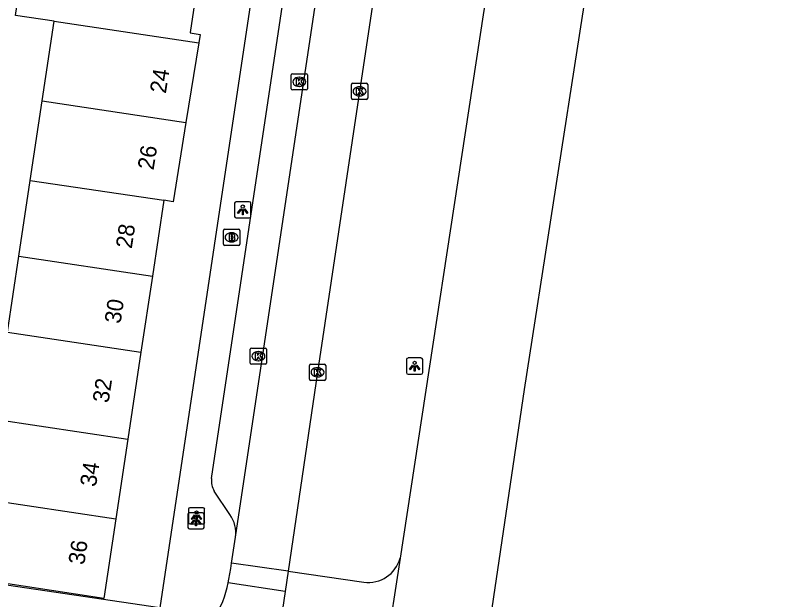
# Model space of a CAD drawing. Extents: x 164150 to 165261, y 382513 to 383432.
# Drawn here: x 164355.91 to 164402.98, y 382748.48 to 382784.41 of the extents above; entities that cross this region are included whole.
import ezdxf

# ---------------------------------------------------------------- set-up
doc = ezdxf.new("R2010")
doc.units = 0
for name, color, linetype in [('IMGEO_Brandkraan', 7, 'Continuous'), ('IMGEO_Kolk', 7, 'Continuous'), ('IMGEO_Lichtpunt', 7, 'Continuous'), ('IMGEO_Pand', 7, 'Continuous'), ('IMGEO_Pand_nummerreeks', 7, 'Continuous'), ('IMGEO_Rijbaan_lokaal_open', 7, 'Continuous'), ('IMGEO_Voetpad_open', 7, 'Continuous')]:
    doc.layers.add(name, color=color, linetype=linetype)

msp = doc.modelspace()

# ---------------------------------------------------------------- linework, layer by layer
at = {"layer": 'IMGEO_Brandkraan'}
for p, q in [((164368.711, 382770.33), (164368.711, 382771.182)), ((164368.786, 382771.256), (164369.638, 382771.256)), ((164369.712, 382771.182), (164369.712, 382770.33)), ((164369.199, 382771.036), (164369.224, 382771.036)), ((164369.638, 382770.256), (164368.786, 382770.256)), ((164369.222, 382770.476), (164369.197, 382770.476))]:
    msp.add_line(p, q, dxfattribs=at)
for points in [[(164368.711, 382770.33), (164368.711, 382771.182)], [(164368.786, 382771.256), (164369.638, 382771.256)], [(164369.712, 382771.182), (164369.712, 382770.33)], [(164369.059, 382770.956), (164369.059, 382770.556), (164369.272, 382770.556)], [(164369.29, 382770.956), (164369.059, 382770.956)], [(164369.238, 382770.875), (164369.184, 382770.875), (164369.184, 382770.799)], [(164369.184, 382770.799), (164369.237, 382770.799)], [(164369.246, 382770.723), (164369.184, 382770.723), (164369.184, 382770.642)], [(164369.184, 382770.642), (164369.246, 382770.642)], [(164369.638, 382770.256), (164368.786, 382770.256)]]:
    msp.add_lwpolyline(points, dxfattribs=at)
for centre, radius, start, end in [((164368.788, 382771.18), 0.0765, 91.552, 178.448), ((164368.788, 382771.18), 0.0765, 91.552, 178.448), ((164369.636, 382771.18), 0.0765, 1.552, 88.448), ((164369.636, 382771.18), 0.0765, 1.552, 88.448), ((164369.239, 382770.837), 0.0379, 267.8285, 90.9355), ((164369.247, 382770.682), 0.0404, 269.8759, 90.5077), ((164369.294, 382770.811), 0.145, 59.4692, 91.5367), ((164369.319, 382770.858), 0.0922, 285.5137, 58.1501), ((164369.324, 382770.666), 0.105, 301.3115, 78.989), ((164368.788, 382770.332), 0.0765, 181.552, 268.448), ((164368.788, 382770.332), 0.0765, 181.552, 268.448), ((164369.278, 382770.807), 0.251, 268.6676, 293.5347), ((164369.636, 382770.332), 0.0765, 271.552, 358.448), ((164369.636, 382770.332), 0.0765, 271.552, 358.448)]:
    msp.add_arc(centre, radius, start, end, dxfattribs=at)
for centre, major_axis, ratio, start_param, end_param in [((164369.198, 382770.756), (-0.387, 0.002), 0.722429, 4.712389, 7.853982), ((164369.223, 382770.756), (-0.39, 0.002), 0.717154, 1.570796, 4.712389)]:
    msp.add_ellipse(centre, major_axis=major_axis, ratio=ratio, start_param=start_param, end_param=end_param, dxfattribs=at)
at = {"layer": 'IMGEO_Kolk'}
for p, q in [((164372.876, 382779.894), (164372.876, 382780.746)), ((164372.951, 382780.82), (164373.803, 382780.82)), ((164373.364, 382780.6), (164373.389, 382780.6)), ((164373.877, 382780.746), (164373.877, 382779.894)), ((164373.387, 382780.04), (164373.362, 382780.04)), ((164376.58, 382779.308), (164376.58, 382780.16)), ((164376.655, 382780.234), (164377.507, 382780.234)), ((164377.068, 382780.014), (164377.093, 382780.014)), ((164377.581, 382780.16), (164377.581, 382779.308)), ((164373.803, 382779.82), (164372.951, 382779.82)), ((164377.507, 382779.234), (164376.655, 382779.234)), ((164377.091, 382779.454), (164377.066, 382779.454)), ((164370.36, 382763.027), (164370.36, 382763.879)), ((164370.435, 382763.953), (164371.287, 382763.953)), ((164370.848, 382763.733), (164370.873, 382763.733)), ((164371.361, 382763.879), (164371.361, 382763.027)), ((164370.871, 382763.173), (164370.846, 382763.173)), ((164371.287, 382762.953), (164370.435, 382762.953)), ((164373.996, 382762.035), (164373.996, 382762.887)), ((164374.071, 382762.961), (164374.923, 382762.961)), ((164374.484, 382762.741), (164374.509, 382762.741)), ((164374.997, 382762.887), (164374.997, 382762.035)), ((164374.507, 382762.181), (164374.482, 382762.181)), ((164374.923, 382761.961), (164374.071, 382761.961))]:
    msp.add_line(p, q, dxfattribs=at)
for points in [[(164372.876, 382779.894), (164372.876, 382780.746)], [(164372.951, 382780.82), (164373.803, 382780.82)], [(164373.197, 382780.52), (164373.32, 382780.52), (164373.32, 382780.369), (164373.45, 382780.52), (164373.614, 382780.52), (164373.468, 382780.369), (164373.621, 382780.12), (164373.469, 382780.12), (164373.384, 382780.284), (164373.32, 382780.217), (164373.32, 382780.12), (164373.197, 382780.12), (164373.197, 382780.52)], [(164373.877, 382780.746), (164373.877, 382779.894)], [(164376.58, 382779.308), (164376.58, 382780.16)], [(164376.655, 382780.234), (164377.507, 382780.234)], [(164377.581, 382780.16), (164377.581, 382779.308)], [(164373.803, 382779.82), (164372.951, 382779.82)], [(164376.901, 382779.934), (164377.024, 382779.934), (164377.024, 382779.783), (164377.154, 382779.934), (164377.318, 382779.934), (164377.172, 382779.783), (164377.325, 382779.534), (164377.173, 382779.534), (164377.088, 382779.698), (164377.024, 382779.631), (164377.024, 382779.534), (164376.901, 382779.534), (164376.901, 382779.934)], [(164377.507, 382779.234), (164376.655, 382779.234)], [(164370.36, 382763.027), (164370.36, 382763.879)], [(164370.435, 382763.953), (164371.287, 382763.953)], [(164370.681, 382763.653), (164370.804, 382763.653), (164370.804, 382763.502), (164370.934, 382763.653), (164371.098, 382763.653), (164370.952, 382763.502), (164371.105, 382763.253), (164370.953, 382763.253), (164370.868, 382763.417), (164370.804, 382763.35), (164370.804, 382763.253), (164370.681, 382763.253), (164370.681, 382763.653)], [(164371.361, 382763.879), (164371.361, 382763.027)], [(164371.287, 382762.953), (164370.435, 382762.953)], [(164373.996, 382762.035), (164373.996, 382762.887)], [(164374.071, 382762.961), (164374.923, 382762.961)], [(164374.317, 382762.661), (164374.44, 382762.661), (164374.44, 382762.51), (164374.57, 382762.661), (164374.734, 382762.661), (164374.588, 382762.51), (164374.741, 382762.261), (164374.589, 382762.261), (164374.504, 382762.425), (164374.44, 382762.358), (164374.44, 382762.261), (164374.317, 382762.261), (164374.317, 382762.661)], [(164374.997, 382762.887), (164374.997, 382762.035)], [(164374.923, 382761.961), (164374.071, 382761.961)]]:
    msp.add_lwpolyline(points, dxfattribs=at)
for centre, start, end in [((164372.953, 382780.744), 91.552, 178.448), ((164372.953, 382780.744), 91.552, 178.448), ((164373.801, 382780.744), 1.552, 88.448), ((164373.801, 382780.744), 1.552, 88.448), ((164376.657, 382780.158), 91.552, 178.448), ((164376.657, 382780.158), 91.552, 178.448), ((164377.505, 382780.158), 1.552, 88.448), ((164377.505, 382780.158), 1.552, 88.448), ((164372.953, 382779.896), 181.552, 268.448), ((164372.953, 382779.896), 181.552, 268.448), ((164373.801, 382779.896), 271.552, 358.448), ((164373.801, 382779.896), 271.552, 358.448), ((164376.657, 382779.31), 181.552, 268.448), ((164376.657, 382779.31), 181.552, 268.448), ((164377.505, 382779.31), 271.552, 358.448), ((164377.505, 382779.31), 271.552, 358.448), ((164370.437, 382763.877), 91.552, 178.448), ((164370.437, 382763.877), 91.552, 178.448), ((164371.285, 382763.877), 1.552, 88.448), ((164371.285, 382763.877), 1.552, 88.448), ((164370.437, 382763.029), 181.552, 268.448), ((164370.437, 382763.029), 181.552, 268.448), ((164371.285, 382763.029), 271.552, 358.448), ((164371.285, 382763.029), 271.552, 358.448), ((164374.073, 382762.885), 91.552, 178.448), ((164374.073, 382762.885), 91.552, 178.448), ((164374.921, 382762.885), 1.552, 88.448), ((164374.921, 382762.885), 1.552, 88.448), ((164374.073, 382762.037), 181.552, 268.448), ((164374.073, 382762.037), 181.552, 268.448), ((164374.921, 382762.037), 271.552, 358.448), ((164374.921, 382762.037), 271.552, 358.448)]:
    msp.add_arc(centre, 0.0765, start, end, dxfattribs=at)
for centre, major_axis, ratio, start_param, end_param in [((164373.363, 382780.32), (-0.387, 0.002), 0.722429, 4.712389, 7.853982), ((164373.388, 382780.32), (-0.39, 0.002), 0.717154, 1.570796, 4.712389), ((164377.067, 382779.734), (-0.387, 0.002), 0.722429, 4.712389, 7.853982), ((164377.092, 382779.734), (-0.39, 0.002), 0.717154, 1.570796, 4.712389), ((164370.847, 382763.453), (-0.387, 0.002), 0.722429, 4.712389, 7.853982), ((164370.872, 382763.453), (-0.39, 0.002), 0.717154, 1.570796, 4.712389), ((164374.483, 382762.461), (-0.387, 0.002), 0.722429, 4.712389, 7.853982), ((164374.508, 382762.461), (-0.39, 0.002), 0.717154, 1.570796, 4.712389)]:
    msp.add_ellipse(centre, major_axis=major_axis, ratio=ratio, start_param=start_param, end_param=end_param, dxfattribs=at)
at = {"layer": 'IMGEO_Lichtpunt'}
for p, q in [((164370.299, 382772.949), (164369.491, 382772.949)), ((164370.299, 382772.949), (164369.491, 382772.949)), ((164369.397, 382772.854), (164369.397, 382772.047)), ((164369.397, 382772.854), (164369.397, 382772.047)), ((164370.393, 382772.047), (164370.393, 382772.854)), ((164370.393, 382772.047), (164370.393, 382772.854)), ((164369.491, 382771.953), (164370.299, 382771.953)), ((164369.491, 382771.953), (164370.299, 382771.953)), ((164379.971, 382763.244), (164379.971, 382762.437)), ((164379.971, 382763.244), (164379.971, 382762.437)), ((164380.873, 382763.339), (164380.065, 382763.339)), ((164380.873, 382763.339), (164380.065, 382763.339)), ((164380.967, 382762.437), (164380.967, 382763.244)), ((164380.967, 382762.437), (164380.967, 382763.244)), ((164380.065, 382762.343), (164380.873, 382762.343)), ((164380.065, 382762.343), (164380.873, 382762.343)), ((164367.46, 382754.13), (164366.652, 382754.13)), ((164367.46, 382754.13), (164366.652, 382754.13)), ((164366.524, 382753.727), (164366.524, 382752.92)), ((164366.524, 382753.727), (164366.524, 382752.92)), ((164366.558, 382754.035), (164366.558, 382753.228)), ((164366.558, 382754.035), (164366.558, 382753.228)), ((164367.426, 382753.822), (164366.618, 382753.822)), ((164367.426, 382753.822), (164366.618, 382753.822)), ((164367.52, 382752.92), (164367.52, 382753.727)), ((164367.52, 382752.92), (164367.52, 382753.727)), ((164367.554, 382753.228), (164367.554, 382754.035)), ((164367.554, 382753.228), (164367.554, 382754.035)), ((164366.618, 382752.826), (164367.426, 382752.826)), ((164366.618, 382752.826), (164367.426, 382752.826)), ((164366.652, 382753.134), (164367.46, 382753.134)), ((164366.652, 382753.134), (164367.46, 382753.134))]:
    msp.add_line(p, q, dxfattribs=at)
for points in [[(164369.771, 382772.518), (164369.81, 382772.49), (164369.622, 382772.228), (164369.584, 382772.255), (164369.771, 382772.518)], [(164369.983, 382772.49), (164370.021, 382772.517), (164370.208, 382772.255), (164370.169, 382772.227), (164369.983, 382772.49)], [(164369.873, 382772.47), (164369.92, 382772.47), (164369.92, 382772.148), (164369.873, 382772.148), (164369.873, 382772.47)], [(164380.345, 382762.908), (164380.384, 382762.88), (164380.196, 382762.618), (164380.158, 382762.645), (164380.345, 382762.908)], [(164380.447, 382762.86), (164380.494, 382762.86), (164380.494, 382762.538), (164380.447, 382762.538), (164380.447, 382762.86)], [(164380.557, 382762.88), (164380.595, 382762.907), (164380.782, 382762.645), (164380.743, 382762.617), (164380.557, 382762.88)], [(164366.932, 382753.699), (164366.971, 382753.671), (164366.783, 382753.409), (164366.745, 382753.436), (164366.932, 382753.699)], [(164367.034, 382753.651), (164367.081, 382753.651), (164367.081, 382753.329), (164367.034, 382753.329), (164367.034, 382753.651)], [(164367.144, 382753.671), (164367.182, 382753.698), (164367.369, 382753.436), (164367.33, 382753.408), (164367.144, 382753.671)], [(164366.898, 382753.391), (164366.937, 382753.363), (164366.749, 382753.101), (164366.711, 382753.128), (164366.898, 382753.391)], [(164367, 382753.343), (164367.047, 382753.343), (164367.047, 382753.021), (164367, 382753.021), (164367, 382753.343)], [(164367.11, 382753.363), (164367.148, 382753.39), (164367.335, 382753.128), (164367.296, 382753.1), (164367.11, 382753.363)]]:
    msp.add_lwpolyline(points, dxfattribs=at)
for centre in [(164369.896, 382772.652), (164380.47, 382763.042), (164367.057, 382753.833), (164367.023, 382753.525)]:
    msp.add_circle(centre, 0.0994, dxfattribs=at)
for centre, start, end in [((164369.491, 382772.854), 90, 180), ((164369.491, 382772.854), 90, 180), ((164370.299, 382772.854), 0, 90), ((164370.299, 382772.854), 0, 90), ((164369.491, 382772.047), 180, 270), ((164369.491, 382772.047), 180, 270), ((164370.299, 382772.047), 270, 0), ((164370.299, 382772.047), 270, 360), ((164380.065, 382763.244), 90, 180), ((164380.065, 382763.244), 90, 180), ((164380.873, 382763.244), 0, 90), ((164380.873, 382763.244), 0, 90), ((164380.065, 382762.437), 180, 270), ((164380.065, 382762.437), 180, 270), ((164380.873, 382762.437), 270, 0), ((164380.873, 382762.437), 270, 360), ((164366.652, 382754.035), 90, 180), ((164366.652, 382754.035), 90, 180), ((164367.46, 382754.035), 0, 90), ((164367.46, 382754.035), 0, 90), ((164366.618, 382753.727), 90, 180), ((164366.618, 382753.727), 90, 180), ((164367.426, 382753.727), 0, 90), ((164367.426, 382753.727), 0, 90), ((164366.652, 382753.228), 180, 270), ((164366.652, 382753.228), 180, 270), ((164367.46, 382753.228), 270, 0), ((164367.46, 382753.228), 270, 360), ((164366.618, 382752.92), 180, 270), ((164366.618, 382752.92), 180, 270), ((164367.426, 382752.92), 270, 0), ((164367.426, 382752.92), 270, 360)]:
    msp.add_arc(centre, 0.0946, start, end, dxfattribs=at)
at = {"layer": 'IMGEO_Pand'}
for points in [[(164358.295, 382784.047), (164355.913, 382784.405), (164356.719, 382789.78), (164359.094, 382789.423)], [(164367.383, 382788.177), (164366.669, 382783.355), (164366.664, 382783.323), (164367.272, 382783.233), (164367.188, 382782.71)], [(164357.561, 382779.154), (164358.295, 382784.047)], [(164358.295, 382784.047), (164367.188, 382782.71)], [(164367.188, 382782.71), (164366.404, 382777.827)], [(164356.827, 382774.26), (164357.561, 382779.154)], [(164357.561, 382779.154), (164366.404, 382777.827)], [(164366.404, 382777.827), (164365.62, 382772.948), (164365.037, 382773.035)], [(164356.128, 382769.598), (164356.827, 382774.26)], [(164356.827, 382774.26), (164365.037, 382773.035)], [(164365.037, 382773.035), (164364.336, 382768.366)], [(164355.428, 382764.929), (164356.128, 382769.598)], [(164356.128, 382769.598), (164364.336, 382768.366)], [(164364.336, 382768.366), (164363.634, 382763.696)], [(164355.428, 382764.929), (164363.634, 382763.696)], [(164363.634, 382763.696), (164362.831, 382758.349)], [(164354.618, 382759.584), (164362.831, 382758.349)], [(164362.831, 382758.349), (164362.095, 382753.455)], [(164362.095, 382753.455), (164361.36, 382748.559), (164353.147, 382749.793), (164353.883, 382754.689)], [(164353.883, 382754.689), (164362.095, 382753.455)]]:
    msp.add_lwpolyline(points, dxfattribs=at)
at = {"layer": 'IMGEO_Rijbaan_lokaal_open'}
for points in [[(164402.983, 382860.898), (164397.573, 382827.291), (164390.779, 382784.365), (164387.209, 382761.399), (164383.845, 382738.669), (164378.996, 382706.807)], [(164388.469, 382855.564), (164387.957, 382852.16), (164384.178, 382827.011), (164381.905, 382811.932), (164379.997, 382799.194), (164379.527, 382795.989), (164377.081, 382779.734), (164374.497, 382762.461), (164372.688, 382750.223)], [(164395.784, 382853.789), (164391.596, 382828.04), (164384.684, 382784.433), (164379.571, 382751.034)], [(164369.459, 382752.322), (164377.452, 382805.647), (164381.703, 382834.004)], [(164369.209, 382750.719), (164369.459, 382752.322)], [(164379.571, 382751.034), (164376.942, 382733.935)], [(164369.004, 382749.522), (164369.041, 382749.737), (164369.158, 382750.397), (164369.209, 382750.719)], [(164372.688, 382750.223), (164369.209, 382750.719)], [(164372.688, 382750.223), (164372.504, 382748.976)], [(164372.688, 382750.223), (164377.348, 382749.559)], [(164372.504, 382748.976), (164369.004, 382749.522)], [(164372.504, 382748.976), (164370.926, 382738.304)]]:
    msp.add_lwpolyline(points, dxfattribs=at)
for centre, radius, start, end in [((164377.627, 382751.551), 2.012, 262.0293, 345.1006), ((164363.105, 382750.636), 6.003, 303.5188, 349.3052)]:
    msp.add_arc(centre, radius, start, end, dxfattribs=at)
at = {"layer": 'IMGEO_Voetpad_open'}
for points in [[(164378.11, 382836.71), (164364.8, 382747.97)], [(164367.98, 382755.927), (164379.235, 382831.014)], [(164369.108, 382753.708), (164368.144, 382755.157)], [(164364.8, 382747.97), (164344.258, 382751.019)]]:
    msp.add_lwpolyline(points, dxfattribs=at)
for centre, radius, start, end in [((164369.068, 382755.756), 1.102, 171.09, 212.9572), ((164367.482, 382752.559), 1.991, 353.1733, 35.2491)]:
    msp.add_arc(centre, radius, start, end, dxfattribs=at)

# ---------------------------------------------------------------- texts
at = {"layer": 'IMGEO_Pand_nummerreeks'}
for s, rotation, p in [('24', 80.873, (164365.163, 382779.566)), ('26', 80.873, (164364.407, 382774.857)), ('28', 81.4574, (164363.069, 382770.028)), ('30', 81.4574, (164362.376, 382765.414)), ('32', 81.4574, (164361.643, 382760.535)), ('34', 81.4574, (164360.869, 382755.385)), ('36', 81.4574, (164360.148, 382750.588))]:
    msp.add_text(s, height=1, rotation=rotation, dxfattribs=at).set_placement(p)

doc.saveas('drawing.dxf')
